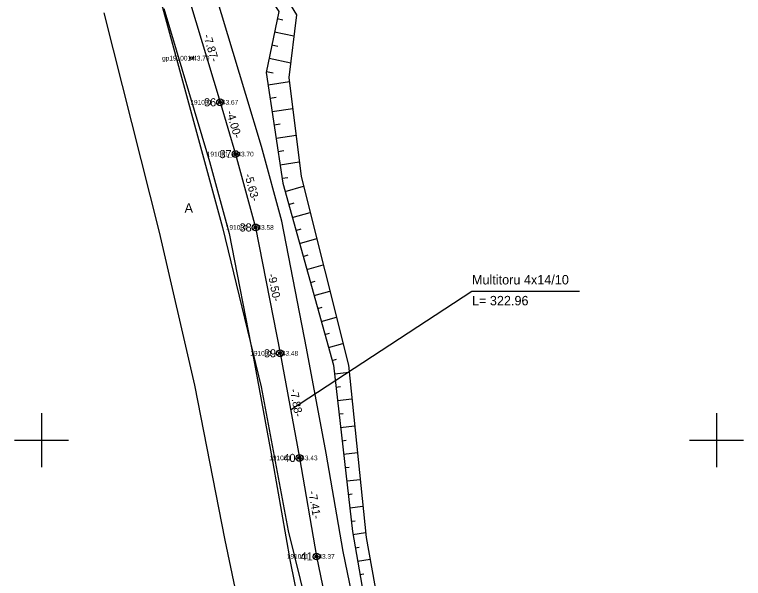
# Model space of a CAD drawing. Extents: x 604066 to 604956, y 6473634 to 6474346.
# Drawn here: x 604648 to 604702, y 6473789.8 to 6473831.5 of the extents above; entities that cross this region are included whole.
import ezdxf

# ---------------------------------------------------------------- set-up
doc = ezdxf.new("R2010")
doc.units = 0
for name, color, linetype in [('JOONSIDE', 7, 'Continuous'), ('KOORDPUNKT', 7, 'Continuous'), ('MOOTKORG', 7, 'Continuous'), ('MOOTMPUNKT', 7, 'Continuous'), ('MOOTNR', 7, 'Continuous'), ('MOOTPIIR', 7, 'Continuous'), ('RELJEEF', 7, 'Continuous'), ('SITRASS', 7, 'Continuous'), ('TEE', 7, 'Continuous'), ('VORK', 7, 'Continuous')]:
    doc.layers.add(name, color=color, linetype=linetype)

msp = doc.modelspace()

# ---------------------------------------------------------------- linework, layer by layer
at = {"layer": 'KOORDPUNKT'}
for centre, radius in [((604663.227, 6473825.022), 0.25), ((604663.227, 6473825.022), 0.025), ((604663.227, 6473825.022), 0.0221), ((604663.227, 6473825.022), 0.0191), ((604663.227, 6473825.022), 0.0161), ((604663.227, 6473825.022), 0.0132), ((604663.227, 6473825.022), 0.0102), ((604663.227, 6473825.022), 0.00726), ((604663.227, 6473825.022), 0.0043), ((604664.375, 6473821.186), 0.25), ((604664.375, 6473821.186), 0.025), ((604664.375, 6473821.186), 0.0221), ((604664.375, 6473821.186), 0.0191), ((604664.375, 6473821.186), 0.0161), ((604664.375, 6473821.186), 0.0132), ((604664.375, 6473821.186), 0.0102), ((604664.375, 6473821.186), 0.00726), ((604664.375, 6473821.186), 0.0043), ((604665.859, 6473815.753), 0.25), ((604665.859, 6473815.753), 0.025), ((604665.859, 6473815.753), 0.0221), ((604665.859, 6473815.753), 0.0191), ((604665.859, 6473815.753), 0.0161), ((604665.859, 6473815.753), 0.0132), ((604665.859, 6473815.753), 0.0102), ((604665.859, 6473815.753), 0.00726), ((604665.859, 6473815.753), 0.0043), ((604667.667, 6473806.431), 0.25), ((604667.667, 6473806.431), 0.025), ((604667.667, 6473806.431), 0.0221), ((604667.667, 6473806.431), 0.0191), ((604667.667, 6473806.431), 0.0161), ((604667.667, 6473806.431), 0.0132), ((604667.667, 6473806.431), 0.0102), ((604667.667, 6473806.431), 0.00726), ((604667.667, 6473806.431), 0.0043), ((604669.108, 6473798.68), 0.25), ((604669.108, 6473798.68), 0.025), ((604669.108, 6473798.68), 0.0221), ((604669.108, 6473798.68), 0.0191), ((604669.108, 6473798.68), 0.0161), ((604669.108, 6473798.68), 0.0132), ((604669.108, 6473798.68), 0.0102), ((604669.108, 6473798.68), 0.00726), ((604669.108, 6473798.68), 0.0043), ((604670.377, 6473791.382), 0.25), ((604670.377, 6473791.382), 0.025), ((604670.377, 6473791.382), 0.0221), ((604670.377, 6473791.382), 0.0191), ((604670.377, 6473791.382), 0.0161), ((604670.377, 6473791.382), 0.0132), ((604670.377, 6473791.382), 0.0102), ((604670.377, 6473791.382), 0.00726), ((604670.377, 6473791.382), 0.0043)]:
    msp.add_circle(centre, radius, dxfattribs=at)
at = {"layer": 'MOOTMPUNKT'}
for centre in [(604661.098, 6473828.291), (604663.227, 6473825.022), (604664.375, 6473821.186), (604665.859, 6473815.753), (604667.667, 6473806.431), (604669.108, 6473798.68), (604670.377, 6473791.382)]:
    msp.add_circle(centre, 0.1, dxfattribs=at)
at = {"layer": 'MOOTPIIR'}
for points in [[(604673.451, 6473786.363), (604672.342, 6473791.755), (604671.076, 6473799.034), (604669.632, 6473806.804), (604667.808, 6473816.208), (604666.298, 6473821.736), (604665.143, 6473825.597), (604662.871, 6473833.15)], [(604659.049, 6473831.968), (604661.311, 6473824.447), (604662.452, 6473820.636), (604663.91, 6473815.298), (604665.702, 6473806.058), (604667.14, 6473798.326), (604668.412, 6473791.009), (604669.609, 6473785.189)]]:
    msp.add_lwpolyline(points, dxfattribs=at)
at = {"layer": 'RELJEEF'}
for p, q in [((604667.466, 6473831.225), (604667.87, 6473831.141)), ((604667.264, 6473830.246), (604668.694, 6473829.95)), ((604667.061, 6473829.267), (604667.515, 6473829.173)), ((604666.858, 6473828.288), (604668.456, 6473827.956)), ((604666.655, 6473827.308), (604667.16, 6473827.204)), ((604666.776, 6473826.32), (604668.363, 6473826.559)), ((604666.925, 6473825.331), (604667.393, 6473825.402)), ((604667.074, 6473824.342), (604668.608, 6473824.573)), ((604667.222, 6473823.354), (604667.675, 6473823.422)), ((604667.371, 6473822.365), (604668.853, 6473822.588)), ((604667.52, 6473821.376), (604667.956, 6473821.441)), ((604667.669, 6473820.387), (604669.097, 6473820.602)), ((604667.817, 6473819.398), (604668.238, 6473819.461)), ((604668.042, 6473818.425), (604669.41, 6473818.807)), ((604668.31, 6473817.462), (604668.713, 6473817.574)), ((604668.578, 6473816.499), (604669.897, 6473816.866)), ((604668.847, 6473815.535), (604669.235, 6473815.643)), ((604669.115, 6473814.572), (604670.384, 6473814.925)), ((604669.383, 6473813.609), (604669.756, 6473813.713)), ((604669.652, 6473812.645), (604670.87, 6473812.985)), ((604669.92, 6473811.682), (604670.278, 6473811.782)), ((604670.188, 6473810.719), (604671.357, 6473811.044)), ((604670.457, 6473809.755), (604670.8, 6473809.851)), ((604670.725, 6473808.792), (604671.844, 6473809.104)), ((604670.993, 6473807.829), (604671.322, 6473807.92)), ((604671.262, 6473806.866), (604672.331, 6473807.163)), ((604671.53, 6473805.902), (604671.843, 6473805.989)), ((604671.7, 6473804.92), (604672.787, 6473805.044)), ((604671.813, 6473803.926), (604672.136, 6473803.963)), ((604671.927, 6473802.933), (604672.992, 6473803.054)), ((604672.04, 6473801.939), (604672.356, 6473801.975)), ((604672.154, 6473800.945), (604673.197, 6473801.065)), ((604672.267, 6473799.952), (604672.577, 6473799.987)), ((604672.38, 6473798.958), (604673.402, 6473799.075)), ((604672.494, 6473797.965), (604672.797, 6473797.999)), ((604672.607, 6473796.971), (604673.607, 6473797.085)), ((604672.72, 6473795.978), (604673.017, 6473796.012)), ((604672.834, 6473794.984), (604673.812, 6473795.096)), ((604672.947, 6473793.991), (604673.237, 6473794.024)), ((604673.073, 6473792.999), (604674.012, 6473793.162)), ((604673.244, 6473792.014), (604673.519, 6473792.061)), ((604673.415, 6473791.028), (604674.336, 6473791.188)), ((604673.586, 6473790.043), (604673.864, 6473790.091))]:
    msp.add_line(p, q, dxfattribs=at)
for points in [[(604653.295, 6473883.776), (604652.349, 6473882.704), (604651.554, 6473874.934), (604652.409, 6473867.668), (604653.905, 6473857.515), (604657.906, 6473844.822), (604660.747, 6473842.118), (604667.575, 6473831.749), (604666.639, 6473827.232), (604667.872, 6473819.034), (604671.628, 6473805.551), (604673.035, 6473793.22), (604675.102, 6473781.297)], [(604653.286, 6473883.779), (604653.187, 6473882.22), (604652.568, 6473875.194), (604653.107, 6473867.861), (604655.174, 6473857.376), (604658.722, 6473845.056), (604661.461, 6473843.005), (604668.228, 6473832.599), (604668.878, 6473831.498)], [(604668.878, 6473831.498), (604668.326, 6473826.862), (604669.23, 6473819.524), (604672.734, 6473805.555), (604674.05, 6473792.791), (604675.939, 6473782.22), (604676.105, 6473781.446)]]:
    msp.add_lwpolyline(points, dxfattribs=at)
at = {"layer": 'SITRASS'}
for points in [[(604660.96, 6473832.559), (604663.227, 6473825.022), (604664.375, 6473821.186), (604665.859, 6473815.753), (604667.667, 6473806.431), (604669.108, 6473798.68), (604670.377, 6473791.382), (604671.53, 6473785.776)], [(604668.448, 6473802.232), (604681.887, 6473811.03), (604689.866, 6473811.03)]]:
    msp.add_lwpolyline(points, dxfattribs=at)
at = {"layer": 'TEE'}
for points in [[(604658.81, 6473832.593), (604663.41, 6473815.739), (604666.276, 6473803.944), (604668.262, 6473793.278), (604670.517, 6473784.167), (604671.08, 6473780.073), (604671.455, 6473778.507), (604672.217, 6473774.119), (604673.164, 6473768.835), (604674.714, 6473758.225), (604677.044, 6473747.391), (604679.117, 6473736.654), (604680.917, 6473727.059), (604681.455, 6473724.996), (604682.501, 6473718.343), (604684.444, 6473711.751), (604685.117, 6473704.62), (604685.813, 6473699.835), (604686.179, 6473697.568), (604688.712, 6473692.868), (604693.859, 6473689.574), (604697.868, 6473688.858)], [(604654.602, 6473831.658), (604658.704, 6473815.393), (604661.338, 6473804.068), (604663.574, 6473792.578), (604666.567, 6473778.333), (604668.535, 6473769.378), (604671.171, 6473757.479), (604673.518, 6473745.143), (604675.484, 6473735.292), (604677.447, 6473724.836), (604678.32, 6473717.488), (604681.05, 6473699.828), (604680.918, 6473696.769), (604679.22, 6473692.841), (604676.23, 6473689.347), (604671.943, 6473687.313)]]:
    msp.add_lwpolyline(points, dxfattribs=at)
at = {"layer": 'VORK'}
for p, q in [((604650, 6473802), (604650, 6473798)), ((604700, 6473802), (604700, 6473798)), ((604648, 6473800), (604652, 6473800)), ((604698, 6473800), (604702, 6473800))]:
    msp.add_line(p, q, dxfattribs=at)

# ---------------------------------------------------------------- texts
at = {"layer": 'JOONSIDE'}
for s, rotation, p in [('-7.87-', 286.7404, (604661.974, 6473829.97)), ('-4.00-', 286.6609, (604663.674, 6473824.312)), ('-5.63-', 285.2774, (604665.027, 6473819.652)), ('-9.50-', 280.9762, (604666.762, 6473812.277)), ('-7.88-', 280.5317, (604668.396, 6473803.741)), ('-7.41-', 279.8642, (604669.77, 6473796.187))]:
    msp.add_text(s, height=0.6, rotation=rotation, dxfattribs=at).set_placement(p)
at = {"layer": 'KOORDPUNKT'}
for s, p in [('36 ', (604662.04, 6473824.722)), ('37 ', (604663.188, 6473820.886)), ('38 ', (604664.672, 6473815.453)), ('39 ', (604666.48, 6473806.131)), ('40 ', (604667.921, 6473798.38)), ('41 ', (604669.185, 6473791.082))]:
    msp.add_text(s, height=0.6, dxfattribs=at).set_placement(p)
at = {"layer": 'MOOTKORG'}
for s, p in [(' 43.79', (604661.098, 6473828.116)), (' 43.67', (604663.227, 6473824.847)), (' 43.70', (604664.375, 6473821.011)), (' 43.58', (604665.859, 6473815.578)), (' 43.48', (604667.667, 6473806.256)), (' 43.43', (604669.108, 6473798.505)), (' 43.37', (604670.377, 6473791.207))]:
    msp.add_text(s, height=0.35, dxfattribs=at).set_placement(p)
at = {"layer": 'MOOTNR'}
for s, p in [('gp1910014 ', (604658.928, 6473828.116)), ('191001_40 ', (604661.022, 6473824.847)), ('191001_41 ', (604662.24, 6473821.011)), ('191001_42 ', (604663.654, 6473815.578)), ('191001_43 ', (604665.462, 6473806.256)), ('191001_44 ', (604666.868, 6473798.505)), ('191001_45 ', (604668.172, 6473791.207))]:
    msp.add_text(s, height=0.35, dxfattribs=at).set_placement(p)
at = {"layer": 'SITRASS'}
for s, p in [('Multitoru 4x14/10 ', (604681.887, 6473811.53)), ('L= 322.96', (604681.887, 6473809.98))]:
    msp.add_text(s, height=0.7, dxfattribs=at).set_placement(p)
at = {"layer": 'TEE'}
msp.add_text('A', height=0.7, dxfattribs=at).set_placement((604660.592, 6473816.846))

doc.saveas('drawing.dxf')
